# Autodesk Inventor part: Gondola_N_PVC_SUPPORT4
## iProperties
Shininess: 64.0
Length Units: 11272
Angle Units: 11279
Time Units: 11290
Mass Units: 11286
Length Display Precision: 3
Angle Display Precision: 2
Compacted: True
Part Number: Gondola_N_PVC_SUPPORT4
Document SubType Name: Modeling
Created: 2004-08
Designer: John Blackburn
Manufacturer: Standard
Standards Organization: Custom
Material: PVC-Piping
Density: 0.0
Volumn: 0.0
Area: 0.0
PropertySet Name: Model Information
Control State: 0
Master: False
Checked Out: False
Author: John Blackburn
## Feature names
1. Base1
